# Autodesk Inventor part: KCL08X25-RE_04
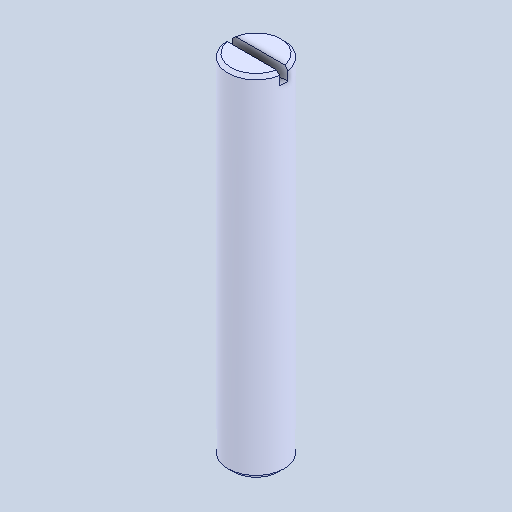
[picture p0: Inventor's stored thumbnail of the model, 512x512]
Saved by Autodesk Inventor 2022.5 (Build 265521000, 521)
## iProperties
Created: 2024-08
Part Number: KCL08X25-RE_04
Material: 一般
Document SubType Name: Modeling
Designer: ImaoCorp
Density: 1 g/cm^3
Appearance: 既定
Author: ImaoCorp
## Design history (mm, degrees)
feature "KCL08X25-RE_04"
node "ソリッド1"
